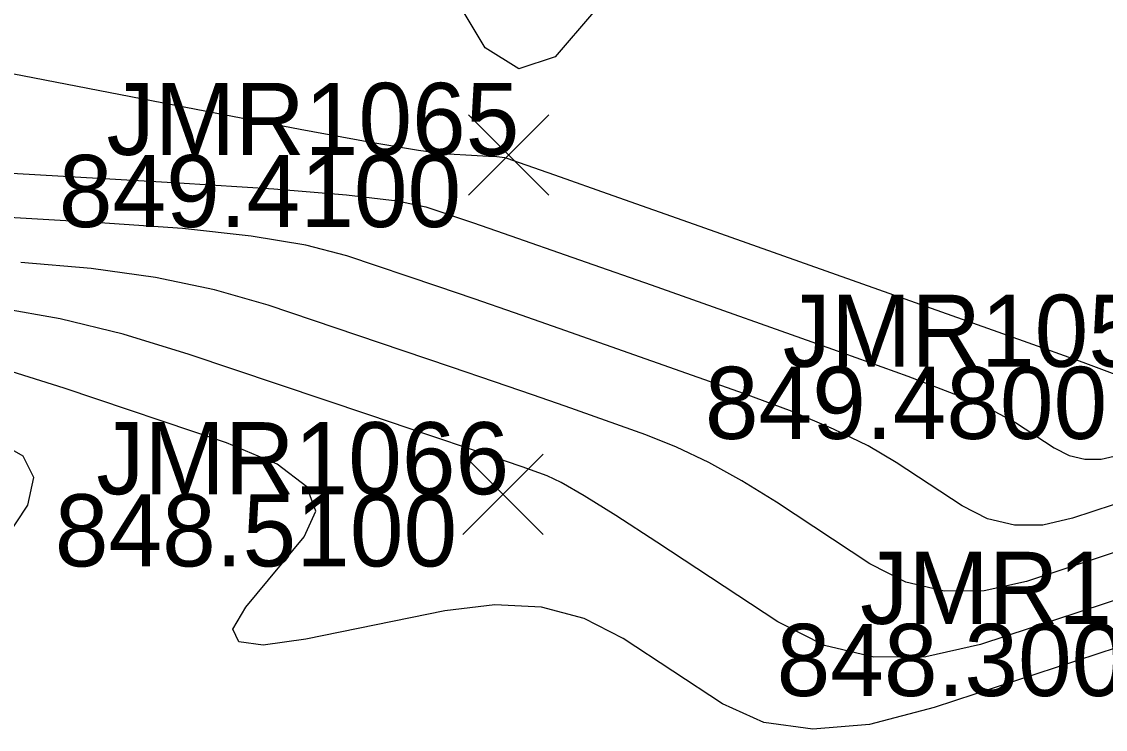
# Model space of a CAD drawing. Extents: x 1654928 to 1810050, y 486881 to 626330.
# Drawn here: x 1801319.88 to 1801337.91, y 489797.47 to 489809.24 of the extents above; entities that cross this region are included whole.
import ezdxf

# ---------------------------------------------------------------- set-up
doc = ezdxf.new("R2010")
doc.units = 0
for name, color, linetype in [('DT_X_Contour_Major', 7, 'Continuous'), ('DT_X_Contour_Minor', 7, 'Continuous'), ('SV_X_Random_Point', 7, 'Continuous'), ('SV_X_Text_Elevation', 7, 'Continuous'), ('SV_X_Text_Name', 7, 'Continuous')]:
    doc.layers.add(name, color=color, linetype=linetype)

msp = doc.modelspace()

# ---------------------------------------------------------------- linework, layer by layer
at = {"layer": 'DT_X_Contour_Major'}
msp.add_lwpolyline([(1801338.718, 489801.424), (1801337.365, 489800.978), (1801336.87, 489800.866), (1801336.398, 489800.863), (1801335.951, 489800.969), (1801335.527, 489801.185), (1801334.429, 489801.908), (1801333.963, 489802.182), (1801333.387, 489802.464), (1801332.702, 489802.753), (1801331.907, 489803.05), (1801328.827, 489804.138), (1801328.083, 489804.397), (1801327.41, 489804.629), (1801326.808, 489804.834), (1801325.296, 489805.344), (1801324.613, 489805.522), (1801323.701, 489805.673), (1801322.559, 489805.798), (1801321.186, 489805.897), (1801317.219, 489806.125)], dxfattribs=at)
at = {"layer": 'DT_X_Contour_Minor'}
for points in [[(1801329.397, 489809.398), (1801328.759, 489808.657), (1801328.157, 489808.46), (1801327.592, 489808.807), (1801327.064, 489809.697), (1801325.707, 489812.797), (1801325.417, 489813.909), (1801325.566, 489814.918), (1801326.153, 489815.826), (1801327.18, 489816.631), (1801329.573, 489818.08)], [(1801318.291, 489808.657), (1801322.961, 489807.753), (1801324.52, 489807.454), (1801325.695, 489807.238), (1801326.485, 489807.103), (1801326.892, 489807.05), (1801327.463, 489807.017), (1801327.652, 489807.006), (1801327.791, 489806.996), (1801327.88, 489806.989), (1801327.919, 489806.983), (1801327.956, 489806.97), (1801328.161, 489806.898), (1801328.749, 489806.691), (1801329.718, 489806.348), (1801331.07, 489805.87), (1801335.185, 489804.415), (1801336.544, 489803.932), (1801337.535, 489803.574), (1801338.156, 489803.341)], [(1801317.799, 489806.832), (1801322.5, 489806.562), (1801324.079, 489806.461), (1801325.29, 489806.361), (1801326.133, 489806.262), (1801326.607, 489806.163), (1801327.382, 489805.902), (1801327.786, 489805.764), (1801329.273, 489805.243), (1801330.356, 489804.861), (1801333.546, 489803.733), (1801334.623, 489803.343), (1801335.461, 489803.019), (1801336.06, 489802.762), (1801336.419, 489802.571), (1801337.06, 489802.149), (1801337.307, 489802.023), (1801337.568, 489801.961), (1801337.843, 489801.963), (1801338.132, 489802.028)], [(1801338.515, 489800.56), (1801336.599, 489799.928), (1801335.897, 489799.769), (1801335.229, 489799.764), (1801334.595, 489799.915), (1801333.995, 489800.222), (1801332.44, 489801.245), (1801331.866, 489801.603), (1801331.313, 489801.909), (1801330.78, 489802.164), (1801330.267, 489802.368), (1801328.927, 489802.842), (1801328.381, 489803.033), (1801327.75, 489803.251), (1801327.035, 489803.495), (1801326.233, 489803.766), (1801323.984, 489804.524), (1801323.094, 489804.782), (1801322.112, 489804.986), (1801321.038, 489805.136), (1801319.872, 489805.232)], [(1801338.312, 489799.696), (1801335.832, 489798.878), (1801334.924, 489798.672), (1801334.06, 489798.666), (1801333.239, 489798.861), (1801332.462, 489799.258), (1801330.45, 489800.582), (1801329.77, 489801.023), (1801329.24, 489801.354), (1801328.859, 489801.575), (1801328.628, 489801.685), (1801328.212, 489801.832), (1801327.935, 489801.928), (1801327.418, 489802.104), (1801326.659, 489802.36), (1801325.659, 489802.698), (1801322.672, 489803.705), (1801321.574, 489804.042), (1801320.523, 489804.298), (1801319.517, 489804.473)], [(1801338.11, 489798.831), (1801335.066, 489797.828), (1801333.989, 489797.549), (1801333.044, 489797.467), (1801332.229, 489797.58), (1801331.544, 489797.89), (1801329.893, 489798.976), (1801329.243, 489799.31), (1801328.532, 489799.499), (1801327.758, 489799.541), (1801326.923, 489799.438), (1801324.613, 489798.969), (1801323.901, 489798.87), (1801323.496, 489798.925), (1801323.4, 489799.134), (1801323.612, 489799.498), (1801324.586, 489800.671), (1801324.78, 489801.099), (1801324.628, 489801.502), (1801324.132, 489801.88), (1801323.292, 489802.234), (1801320.591, 489803.144), (1801319.623, 489803.448)], [(1801319.611, 489800.628), (1801319.987, 489801.195), (1801320.087, 489801.656), (1801319.91, 489802.013), (1801319.458, 489802.265)]]:
    msp.add_lwpolyline(points, dxfattribs=at)
at = {"layer": 'SV_X_Random_Point'}
for p, q in [((1801327.318, 489806.356), (1801328.652, 489807.691)), ((1801327.318, 489807.691), (1801328.652, 489806.356)), ((1801327.224, 489800.71), (1801328.557, 489802.046)), ((1801327.224, 489802.046), (1801328.557, 489800.71))]:
    msp.add_line(p, q, dxfattribs=at)

# ---------------------------------------------------------------- texts
at = {"layer": 'SV_X_Text_Elevation'}
for s, p in [('849.4100', (1801320.503, 489805.824)), ('849.4800', (1801331.25, 489802.299)), ('848.5100', (1801320.436, 489800.178)), ('848.3000', (1801332.443, 489798.021))]:
    msp.add_text(s, height=1.2, dxfattribs=at).set_placement(p)
at = {"layer": 'SV_X_Text_Name'}
for s, p in [('JMR1065', (1801321.296, 489807.024)), ('JMR1054', (1801332.545, 489803.499)), ('JMR1066', (1801321.126, 489801.378)), ('JMR1053', (1801333.833, 489799.221))]:
    msp.add_text(s, height=1.2, dxfattribs=at).set_placement(p)

doc.saveas('drawing.dxf')
